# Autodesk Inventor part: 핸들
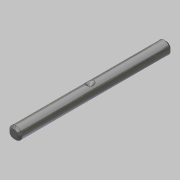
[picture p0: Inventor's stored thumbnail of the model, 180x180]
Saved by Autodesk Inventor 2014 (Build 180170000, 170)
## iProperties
Created: 2019-04
Part Number: 핸들
Material: 스테인리스강
Document SubType Name: Modeling
Designer: mduedu
Density: 1 g/cm^3
Appearance: 반광택
Author: mduedu
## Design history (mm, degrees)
sketch "스케치1"
  geometry: C1 r 3 at (0, 0); 1 further point
  constraints: 1 centre point, 1 coincident
  dimensions: "d0" = 6 diameter of C1
extrude "돌출1" new body sketch "스케치1" stored distance "d1" = 74; taper "d2" = 0 deg
chamfer "모따기1" distance "d3" = 1; stored, may be unused: second distance "d4" = 2, angle "d5" = 45 deg
sketch "스케치2"
  geometry: L1 (-36, 3)-(36, 3) reference; L2 (0, 3)-(0, 1); L3 (0, 1)-(2, 3); L4 (0, 3)-(2, 3); 1 further point
  constraints: 6 end point, 2 perpendicular, 1 midpoint, 1 point on line
  dimensions: "d6" = 4 diameter of L3.end L2; "d8" = 45 deg angle of L3 L2
revolve "회전1" sketch "스케치2" stored, may be unused: angle "d10" = 90 deg
node "작업점1"
  node "작업축1"
  node "작업 평면1"
workpoint "Work Point2"
  workaxis "Work Axis2"
node "솔리드1"
